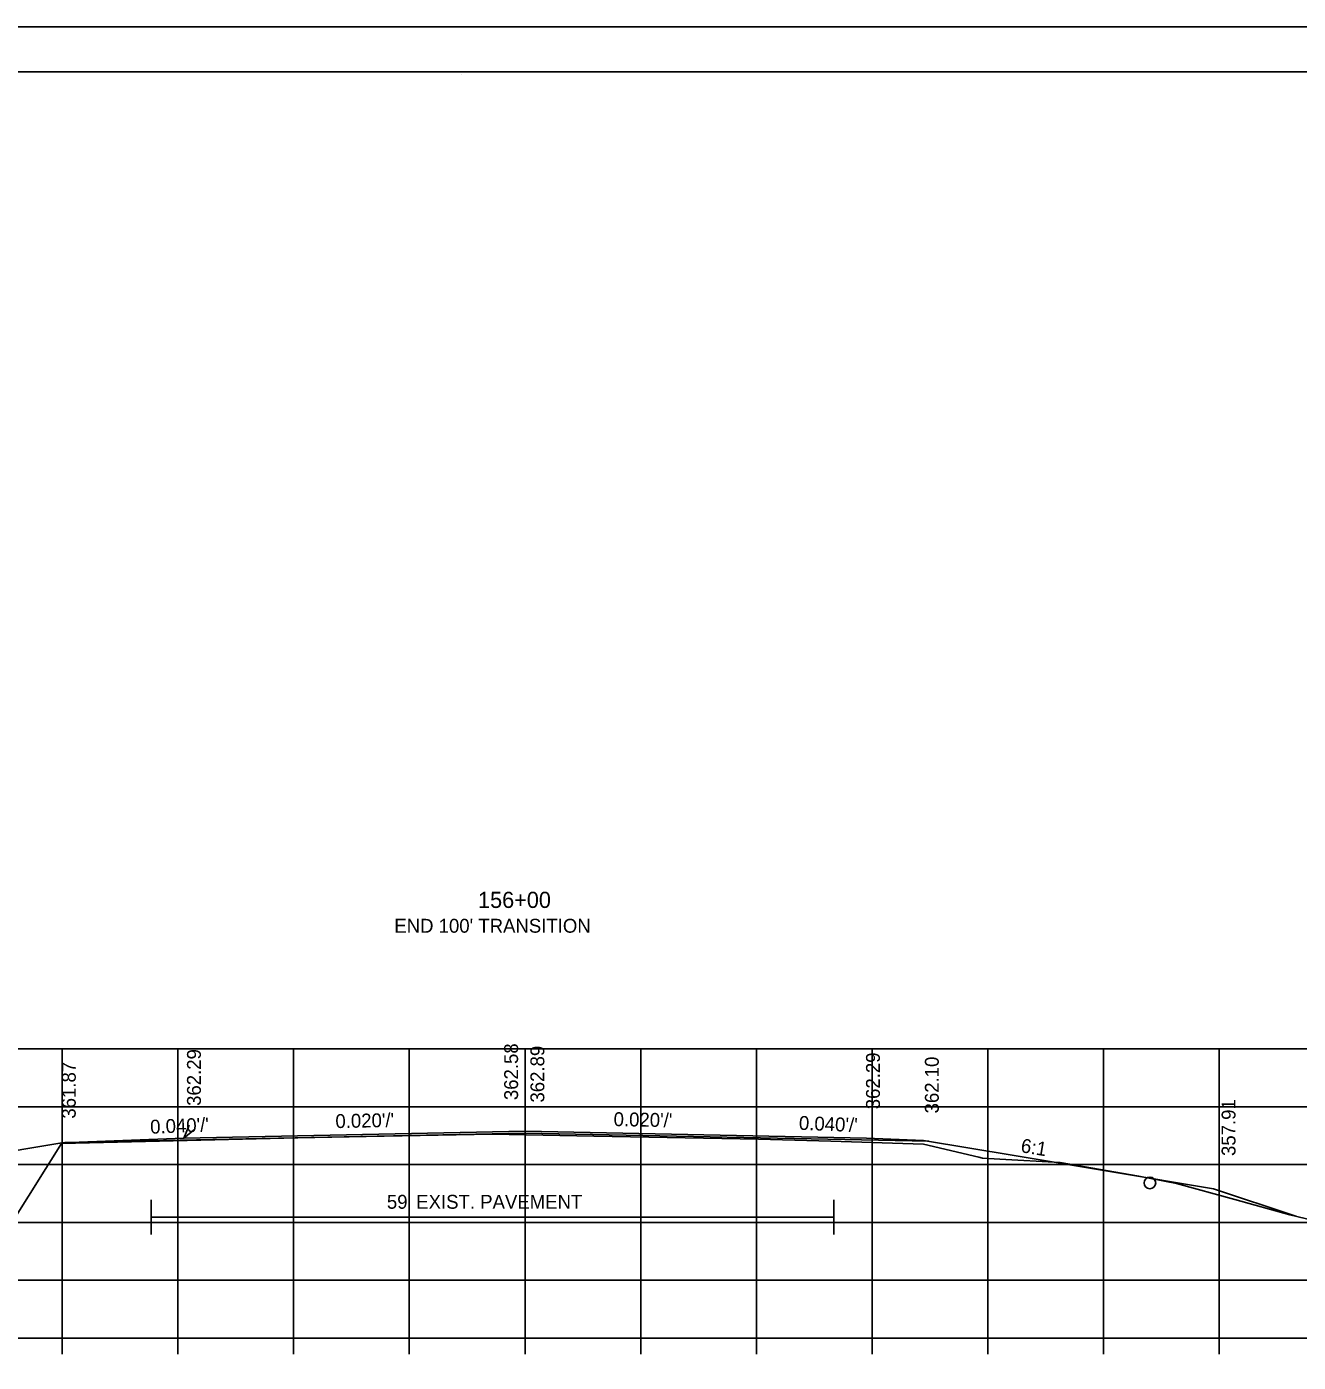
# Model space of a CAD drawing. Extents: x 1374859 to 1376773, y 382242 to 389804.
# Drawn here: x 1376091.5 to 1376201.4, y 386819.7 to 386935.2 of the extents above; entities that cross this region are included whole.
import ezdxf

# ---------------------------------------------------------------- set-up
doc = ezdxf.new("R2010")
doc.units = 0
for name, color, linetype in [('R_Axis', 7, 'Continuous'), ('R_Axis Annot', 7, 'Continuous'), ('R_Border', 7, 'Continuous'), ('R_Border Notes', 7, 'Continuous'), ('R_Exist Surface', 7, 'Continuous'), ('R_Fin Surface', 7, 'Continuous'), ('R_Grid', 7, 'Continuous'), ('R_No Plot', 7, 'Continuous'), ('R_Proposed Road', 7, 'Continuous'), ('R_Xsect Elev', 7, 'Continuous'), ('R_Xsect Slope', 7, 'Continuous')]:
    doc.layers.add(name, color=color, linetype=linetype)

msp = doc.modelspace()

# ---------------------------------------------------------------- linework, layer by layer
at = {"layer": 'R_Axis'}
for p, q in [((1375994.57, 386821.82), (1376274.57, 386821.82)), ((1376094.57, 386820.42), (1376094.57, 386821.82)), ((1376104.57, 386820.42), (1376104.57, 386821.82)), ((1376114.57, 386820.42), (1376114.57, 386821.82)), ((1376124.57, 386820.42), (1376124.57, 386821.82)), ((1376134.57, 386820.42), (1376134.57, 386821.82)), ((1376144.57, 386820.42), (1376144.57, 386821.82)), ((1376154.57, 386820.42), (1376154.57, 386821.82)), ((1376164.57, 386820.42), (1376164.57, 386821.82)), ((1376174.57, 386820.42), (1376174.57, 386821.82)), ((1376184.57, 386820.42), (1376184.57, 386821.82)), ((1376194.57, 386820.42), (1376194.57, 386821.82))]:
    msp.add_line(p, q, dxfattribs=at)
at = {"layer": 'R_Border'}
for p, q in [((1375976.57, 386931.28), (1376292.75, 386931.28)), ((1376129.09, 386931.02), (1376129.09, 386931.02)), ((1376129.09, 386931.02), (1376129.09, 386931.02))]:
    msp.add_line(p, q, dxfattribs=at)
at = {"layer": 'R_Border Notes'}
for points in [[(1376102.26, 386833.78), (1376102.26, 386830.78)], [(1376161.26, 386833.78), (1376161.26, 386830.78)], [(1376102.26, 386832.28), (1376161.26, 386832.28)]]:
    msp.add_lwpolyline(points, dxfattribs=at)
at = {"layer": 'R_Exist Surface'}
for points in [[(1376105.55, 386840.22), (1376105.09, 386839.11), (1376106.02, 386839.87)], [(1376090.3, 386831.93), (1376094.51, 386838.64), (1376102.96, 386838.84), (1376114.92, 386839.14), (1376120.85, 386839.25), (1376131.74, 386839.45), (1376140.53, 386839.27), (1376154.75, 386839.02), (1376161, 386838.84), (1376169.01, 386838.59), (1376173.8, 386837.45), (1376174.13, 386837.38), (1376175.61, 386837.3), (1376180.83, 386837.01), (1376187.62, 386835.81), (1376190.9, 386835.18), (1376195.94, 386833.8), (1376200.7, 386832.48), (1376206.59, 386831.07)]]:
    msp.add_lwpolyline(points, dxfattribs=at)
at = {"layer": 'R_Fin Surface'}
for points in [[(1376054.93, 386829.9), (1376056.69, 386829.32), (1376075.09, 386835.45), (1376087.43, 386837.51), (1376094.52, 386838.69), (1376105.09, 386839.11), (1376134.59, 386839.7), (1376164.09, 386839.11), (1376169.01, 386838.91), (1376176.85, 386837.61), (1376194.09, 386834.73), (1376201.22, 386832.36)], [(1376094.8, 386838.73), (1376134.58, 386839.53), (1376169.49, 386838.83)]]:
    msp.add_lwpolyline(points, dxfattribs=at)
at = {"layer": 'R_Grid'}
for p, q in [((1375994.57, 386846.82), (1376274.57, 386846.82)), ((1376094.57, 386821.82), (1376094.57, 386846.82)), ((1376104.57, 386821.82), (1376104.57, 386846.82)), ((1376114.57, 386821.82), (1376114.57, 386846.82)), ((1376124.57, 386821.82), (1376124.57, 386846.82)), ((1376134.57, 386821.82), (1376134.57, 386846.82)), ((1376144.57, 386821.82), (1376144.57, 386846.82)), ((1376154.57, 386821.82), (1376154.57, 386846.82)), ((1376164.57, 386821.82), (1376164.57, 386846.82)), ((1376174.57, 386821.82), (1376174.57, 386846.82)), ((1376184.57, 386821.82), (1376184.57, 386846.82)), ((1376194.57, 386821.82), (1376194.57, 386846.82)), ((1375994.57, 386841.82), (1376274.57, 386841.82)), ((1375994.57, 386836.82), (1376274.57, 386836.82)), ((1375994.57, 386831.82), (1376274.57, 386831.82)), ((1375994.57, 386826.82), (1376274.57, 386826.82)), ((1375994.57, 386821.82), (1376274.57, 386821.82))]:
    msp.add_line(p, q, dxfattribs=at)
at = {"layer": 'R_No Plot'}
msp.add_line((1375964.17, 386935.17), (1376297.5, 386935.17), dxfattribs=at)
for points in [[(1375964.16, 386935.17), (1376297.5, 386935.17), (1376297.5, 386721.84), (1375964.16, 386721.84)], [(1376210.49, 386931.28), (1376210.49, 386921.4), (1376246.22, 386921.4), (1376246.22, 386918.48), (1376269.42, 386918.48), (1376269.42, 386894.15), (1376292.75, 386894.15), (1376292.75, 386725.82), (1375976.57, 386725.82), (1375976.57, 386931.28)]]:
    msp.add_lwpolyline(points, close=True, dxfattribs=at)
msp.add_circle((1376188.59, 386835.23), 0.5, dxfattribs=at)

# ---------------------------------------------------------------- texts
at = {"layer": 'R_Axis Annot'}
msp.add_text('156+00', height=1.4, dxfattribs=at).set_placement((1376130.51, 386859))
at = {"layer": 'R_Border Notes'}
msp.add_text("59' EXIST. PAVEMENT", height=1.2, rotation=0, dxfattribs=at).set_placement((1376122.63, 386833))
at = {"layer": 'R_Proposed Road'}
msp.add_text("END 100' TRANSITION", height=1.2, dxfattribs=at).set_placement((1376123.27, 386856.86))
at = {"layer": 'R_Xsect Elev'}
for s, p in [('362.29', (1376106.55, 386841.89)), ('362.58', (1376133.97, 386842.39)), ('362.89', (1376136.24, 386842.18)), ('361.87', (1376095.73, 386840.79)), ('362.29', (1376165.25, 386841.6)), ('362.10', (1376170.34, 386841.24)), ('357.91', (1376195.99, 386837.56))]:
    msp.add_text(s, height=1.2, rotation=90, dxfattribs=at).set_placement(p)
at = {"layer": 'R_Xsect Slope'}
for s, rotation, p in [("0.040'/'", 2.2906, (1376102.19, 386839.48)), ("0.020'/'", 1.1458, (1376118.19, 386839.97)), ("0.020'/'", 358.8542, (1376142.22, 386840.15)), ("0.040'/'", 357.7094, (1376158.23, 386839.83)), ('6:1', 350.5358, (1376177.37, 386837.9))]:
    msp.add_text(s, height=1.2, rotation=rotation, dxfattribs=at).set_placement(p)

doc.saveas('drawing.dxf')
